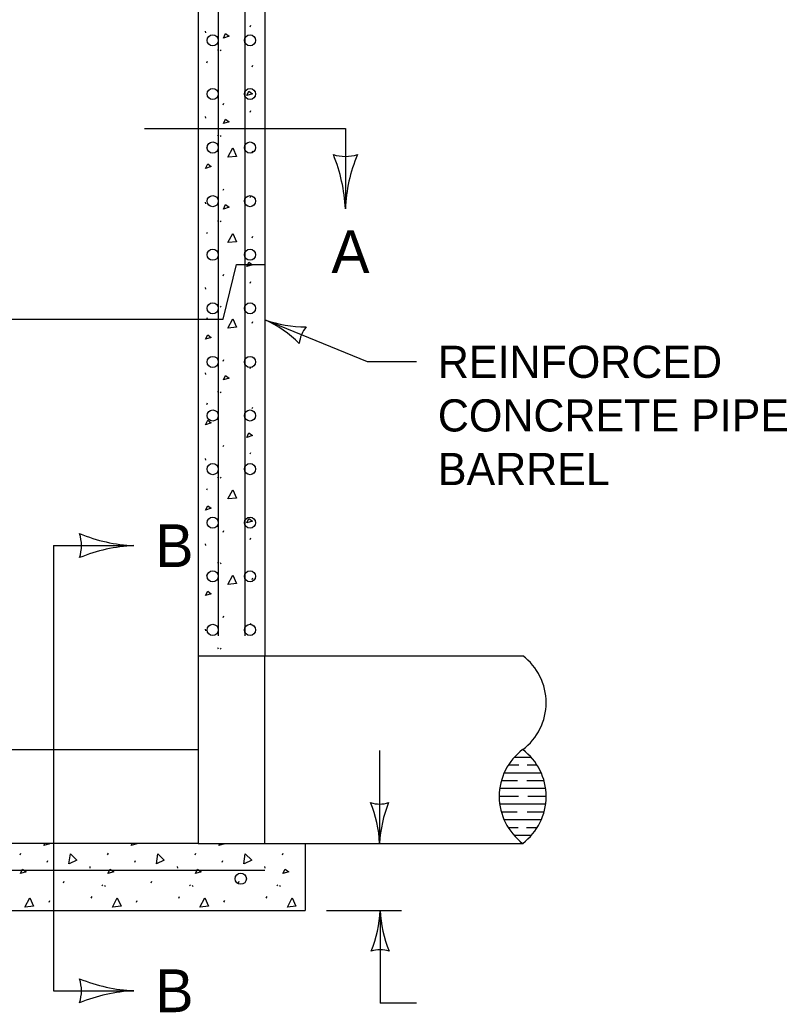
# Model space of a CAD drawing. Extents: x 49991.4 to 50028.3, y 49987.6 to 50011.4.
# Drawn here: x 50026.881 to 50028.313, y 49989.113 to 49990.964 of the extents above; entities that cross this region are included whole.
import ezdxf

# ---------------------------------------------------------------- set-up
doc = ezdxf.new("R2010")
doc.units = 0
for name, color, linetype in [('Level 1', 7, 'Continuous'), ('Level 2', 7, 'Continuous'), ('Level 3', 7, 'Continuous'), ('Level 4', 7, 'Continuous'), ('Level 6', 7, 'Continuous')]:
    doc.layers.add(name, color=color, linetype=linetype)

msp = doc.modelspace()

# ---------------------------------------------------------------- linework, layer by layer
at = {"layer": 'Level 1'}
for p, q in [((50027.3384, 49991.4777), (50027.3384, 49989.7777)), ((50027.2509, 49991.4401), (50027.2509, 49989.8151)), ((50027.3009, 49991.4401), (50027.3009, 49989.8151)), ((50027.2268, 49990.9433), (50027.2271, 49990.9403)), ((50027.3109, 49990.9516), (50027.3122, 49990.9546)), ((50027.2495, 49990.9091), (50027.2509, 49990.9071)), ((50027.2546, 49990.9083), (50027.2559, 49990.9063)), ((50027.2299, 49990.8844), (50027.2312, 49990.8874)), ((50027.3142, 49990.8767), (50027.3156, 49990.8797)), ((50027.2603, 49990.8058), (50027.2616, 49990.8088)), ((50027.3109, 49990.7922), (50027.3122, 49990.7952)), ((50027.2268, 49990.7838), (50027.2271, 49990.7808)), ((50027.2495, 49990.7497), (50027.2509, 49990.7477)), ((50027.2546, 49990.7489), (50027.2559, 49990.7469)), ((50027.2299, 49990.7249), (50027.2312, 49990.7279)), ((50027.3142, 49990.7173), (50027.3156, 49990.7203)), ((50027.2603, 49990.6464), (50027.2616, 49990.6494)), ((50027.2268, 49990.6243), (50027.2271, 49990.6213)), ((50027.3109, 49990.6327), (50027.3122, 49990.6357)), ((50027.2495, 49990.5902), (50027.2509, 49990.5882)), ((50027.2546, 49990.5894), (50027.2559, 49990.5874)), ((50027.2299, 49990.5655), (50027.2312, 49990.5685)), ((50027.3142, 49990.5579), (50027.3156, 49990.5609)), ((50027.2602, 49990.4059), (50027.2855, 49990.5077)), ((50027.2855, 49990.5077), (50027.3384, 49990.5077)), ((50027.2603, 49990.4869), (50027.2616, 49990.4899)), ((50027.3109, 49990.4733), (50027.3122, 49990.4763)), ((50027.2268, 49990.4649), (50027.2271, 49990.4619)), ((50027.2495, 49990.4307), (50027.2509, 49990.4287)), ((50027.2546, 49990.43), (50027.2559, 49990.428)), ((50025.9916, 49990.4059), (50027.2602, 49990.4059)), ((50027.2299, 49990.4061), (50027.2312, 49990.4091)), ((50027.3142, 49990.3984), (50027.3156, 49990.4014)), ((50027.2603, 49990.3275), (50027.2616, 49990.3305)), ((50027.3109, 49990.3138), (50027.3122, 49990.3168)), ((50027.2268, 49990.3055), (50027.2271, 49990.3025)), ((50027.2495, 49990.2713), (50027.2509, 49990.2693)), ((50027.2546, 49990.2705), (50027.2559, 49990.2685)), ((50027.2299, 49990.2466), (50027.2312, 49990.2496)), ((50027.3142, 49990.2389), (50027.3156, 49990.2419)), ((50027.2603, 49990.168), (50027.2616, 49990.171)), ((50027.2268, 49990.146), (50027.2271, 49990.143)), ((50027.3109, 49990.1543), (50027.3122, 49990.1573)), ((50027.2495, 49990.1118), (50027.2509, 49990.1098)), ((50027.2546, 49990.1111), (50027.2559, 49990.1091)), ((50027.2299, 49990.0871), (50027.2312, 49990.0901)), ((50027.2603, 49990.0085), (50027.2616, 49990.0115)), ((50027.3109, 49989.9949), (50027.3122, 49989.9979)), ((50027.2268, 49989.9865), (50027.2271, 49989.9835)), ((50027.2495, 49989.9524), (50027.2509, 49989.9504)), ((50027.2546, 49989.9516), (50027.2559, 49989.9496)), ((50027.2299, 49989.9277), (50027.2312, 49989.9307)), ((50027.3142, 49989.92), (50027.3156, 49989.923)), ((50027.2603, 49989.8491), (50027.2616, 49989.8521)), ((50027.2268, 49989.8271), (50027.2271, 49989.8241)), ((50027.3109, 49989.8355), (50027.3122, 49989.8385)), ((50027.2495, 49989.7929), (50027.2509, 49989.7909)), ((50027.2546, 49989.7921), (50027.2559, 49989.7901)), ((50027.2134, 49989.7777), (50027.8193, 49989.7777)), ((50026.0384, 49989.6027), (50027.2134, 49989.6027)), ((50027.8352, 49989.5882), (50027.8034, 49989.5882)), ((50027.8122, 49989.5736), (50027.7924, 49989.5736)), ((50027.8462, 49989.5736), (50027.8279, 49989.5736)), ((50027.8539, 49989.559), (50027.7846, 49989.559)), ((50027.8099, 49989.5444), (50027.7795, 49989.5444)), ((50027.8591, 49989.5444), (50027.8271, 49989.5444)), ((50027.8115, 49989.5152), (50027.7755, 49989.5152)), ((50027.8621, 49989.5298), (50027.7765, 49989.5298)), ((50027.863, 49989.5152), (50027.8287, 49989.5152)), ((50027.8621, 49989.5007), (50027.7765, 49989.5007)), ((50027.8092, 49989.4861), (50027.7795, 49989.4861)), ((50027.8591, 49989.4861), (50027.8279, 49989.4861)), ((50027.8539, 49989.4715), (50027.7846, 49989.4715)), ((50027.8108, 49989.4569), (50027.7924, 49989.4569)), ((50027.8462, 49989.4569), (50027.8264, 49989.4569)), ((50027.8352, 49989.4423), (50027.8034, 49989.4423)), ((50027.2134, 49989.4277), (50027.8193, 49989.4277)), ((50027.4134, 49989.4277), (50027.4134, 49989.3027)), ((50026.8815, 49989.4064), (50026.8828, 49989.4094)), ((50027.0447, 49989.4064), (50027.0461, 49989.4094)), ((50027.208, 49989.4064), (50027.2093, 49989.4094)), ((50027.3713, 49989.4064), (50027.3726, 49989.4094)), ((50026.9321, 49989.3928), (50026.9334, 49989.3958)), ((50027.0113, 49989.3844), (50027.0116, 49989.3814)), ((50027.0953, 49989.3928), (50027.0967, 49989.3958)), ((50027.1745, 49989.3844), (50027.1749, 49989.3814)), ((50027.2586, 49989.3928), (50027.2599, 49989.3958)), ((50027.3378, 49989.3844), (50027.3381, 49989.3814)), ((50025.9134, 49989.3777), (50027.3384, 49989.3777)), ((50026.9624, 49989.3541), (50026.9637, 49989.3571)), ((50027.034, 49989.3503), (50027.0353, 49989.3483)), ((50027.0391, 49989.3495), (50027.0404, 49989.3475)), ((50027.1257, 49989.3541), (50027.127, 49989.3571)), ((50027.1973, 49989.3503), (50027.1986, 49989.3483)), ((50027.2023, 49989.3495), (50027.2037, 49989.3475)), ((50027.2889, 49989.3541), (50027.2903, 49989.3571)), ((50027.3605, 49989.3503), (50027.3619, 49989.3483)), ((50027.3656, 49989.3495), (50027.3669, 49989.3475)), ((50027.0143, 49989.3256), (50027.0157, 49989.3285)), ((50027.1776, 49989.3256), (50027.1789, 49989.3285)), ((50027.3409, 49989.3256), (50027.3422, 49989.3285)), ((50026.9354, 49989.3179), (50026.9367, 49989.3209)), ((50027.0987, 49989.3179), (50027.1, 49989.3209)), ((50027.2619, 49989.3179), (50027.2633, 49989.3209)), ((50025.8384, 49989.3027), (50027.4134, 49989.3027))]:
    msp.add_line(p, q, dxfattribs=at)
msp.add_lwpolyline([(50026.0384, 49991.4777), (50027.2134, 49991.4777), (50027.2134, 49989.4277), (50026.0384, 49989.4277)], close=True, dxfattribs=at)
for points in [[(50027.2609, 49990.9303), (50027.2649, 49990.9387), (50027.2716, 49990.9337), (50027.2609, 49990.9303)], [(50027.3043, 49990.823), (50027.3083, 49990.8313), (50027.315, 49990.8263), (50027.3043, 49990.823)], [(50027.2609, 49990.7709), (50027.2649, 49990.7792), (50027.2716, 49990.7742), (50027.2609, 49990.7709)], [(50027.2693, 49990.7083), (50027.2783, 49990.7253), (50027.2853, 49990.7097), (50027.2696, 49990.7083)], [(50027.2275, 49990.6873), (50027.2315, 49990.6957), (50027.2382, 49990.6907), (50027.2275, 49990.6873)], [(50027.2609, 49990.6114), (50027.2649, 49990.6197), (50027.2716, 49990.6147), (50027.2609, 49990.6114)], [(50027.2693, 49990.5489), (50027.2783, 49990.5659), (50027.2853, 49990.5502), (50027.2696, 49990.5489)], [(50027.3043, 49990.5041), (50027.3083, 49990.5124), (50027.315, 49990.5074), (50027.3043, 49990.5041)], [(50027.2693, 49990.3894), (50027.2783, 49990.4064), (50027.2853, 49990.3907), (50027.2696, 49990.3894)], [(50027.2275, 49990.3684), (50027.2315, 49990.3767), (50027.2382, 49990.3717), (50027.2275, 49990.3684)], [(50027.2609, 49990.2925), (50027.2649, 49990.3008), (50027.2716, 49990.2958), (50027.2609, 49990.2925)], [(50027.2275, 49990.209), (50027.2315, 49990.2173), (50027.2382, 49990.2123), (50027.2275, 49990.209)], [(50027.3043, 49990.1851), (50027.3083, 49990.1935), (50027.315, 49990.1885), (50027.3043, 49990.1851)], [(50027.2693, 49990.0705), (50027.2783, 49990.0875), (50027.2853, 49990.0718), (50027.2696, 49990.0705)], [(50027.2275, 49990.0495), (50027.2315, 49990.0578), (50027.2382, 49990.0529), (50027.2275, 49990.0495)], [(50027.3043, 49990.0257), (50027.3083, 49990.034), (50027.315, 49990.029), (50027.3043, 49990.0257)], [(50027.2693, 49989.911), (50027.2783, 49989.928), (50027.2853, 49989.9124), (50027.2696, 49989.911)], [(50027.2275, 49989.8901), (50027.2315, 49989.8984), (50027.2382, 49989.8934), (50027.2275, 49989.8901)], [(50026.9255, 49989.4236), (50026.9274, 49989.4277)], [(50026.9351, 49989.4277), (50026.9361, 49989.4269), (50026.9255, 49989.4236)], [(50027.0887, 49989.4236), (50027.0907, 49989.4277)], [(50027.0984, 49989.4277), (50027.0994, 49989.4269), (50027.0887, 49989.4236)], [(50027.252, 49989.4236), (50027.2539, 49989.4277)], [(50027.2617, 49989.4277), (50027.2627, 49989.4269), (50027.252, 49989.4236)], [(50026.9726, 49989.3893), (50026.9752, 49989.4084), (50026.9871, 49989.3961), (50026.9729, 49989.3895)], [(50027.1359, 49989.3893), (50027.1385, 49989.4084), (50027.1504, 49989.3961), (50027.1362, 49989.3895)], [(50027.2991, 49989.3893), (50027.3017, 49989.4084), (50027.3137, 49989.3961), (50027.2994, 49989.3895)], [(50026.8821, 49989.3715), (50026.8861, 49989.3798), (50026.8928, 49989.3748), (50026.8821, 49989.3715)], [(50027.0454, 49989.3715), (50027.0494, 49989.3798), (50027.0561, 49989.3748), (50027.0454, 49989.3715)], [(50027.2087, 49989.3715), (50027.2127, 49989.3798), (50027.2193, 49989.3748), (50027.2087, 49989.3715)], [(50027.3719, 49989.3715), (50027.3759, 49989.3798), (50027.3826, 49989.3748), (50027.3719, 49989.3715)], [(50026.8905, 49989.3089), (50026.8995, 49989.3259), (50026.9064, 49989.3103), (50026.8908, 49989.3089)], [(50027.0537, 49989.3089), (50027.0627, 49989.3259), (50027.0697, 49989.3103), (50027.0541, 49989.3089)], [(50027.217, 49989.3089), (50027.226, 49989.3259), (50027.233, 49989.3103), (50027.2173, 49989.3089)], [(50027.3803, 49989.3089), (50027.3892, 49989.3259), (50027.3962, 49989.3103), (50027.3806, 49989.3089)]]:
    msp.add_lwpolyline(points, dxfattribs=at)
for centre in [(50027.2409, 49990.9261), (50027.3105, 49990.9261), (50027.2409, 49990.8261), (50027.3105, 49990.8261), (50027.2409, 49990.7261), (50027.3105, 49990.7261), (50027.2409, 49990.6261), (50027.3105, 49990.6261), (50027.2409, 49990.5261), (50027.3105, 49990.5261), (50027.2409, 49990.4261), (50027.3105, 49990.4261), (50027.2409, 49990.3261), (50027.3105, 49990.3261), (50027.2409, 49990.2261), (50027.3105, 49990.2261), (50027.2409, 49990.1261), (50027.3105, 49990.1261), (50027.2409, 49990.0261), (50027.3105, 49990.0261), (50027.2409, 49989.9261), (50027.3105, 49989.9261), (50027.2409, 49989.8261), (50027.3105, 49989.8261), (50027.2932, 49989.3617)]:
    msp.add_circle(centre, 0.0104, dxfattribs=at)
for centre, start, end in [((50027.7537, 49989.6902), 306.8699, 53.1301), ((50027.8849, 49989.5152), 126.8699, 233.1301), ((50027.7537, 49989.5152), 306.8699, 53.1301)]:
    msp.add_arc(centre, 0.1094, start, end, dxfattribs=at)
at = {"layer": 'Level 3'}
for p, q in [((50027.5298, 49990.3263), (50027.3384, 49990.4046)), ((50027.621, 49990.3263), (50027.5298, 49990.3263)), ((50027.5524, 49989.6011), (50027.5524, 49989.4277)), ((50027.4534, 49989.3027), (50027.5934, 49989.3027)), ((50027.5534, 49989.3027), (50027.5534, 49989.1293)), ((50027.621, 49989.1293), (50027.5534, 49989.1293))]:
    msp.add_line(p, q, dxfattribs=at)
for centre, radius, start, end in [((50027.4884, 49990.7826), 0.073, 252.1388, 287.8612), ((50027.1781, 49990.5963), 0.3107, 2.8273, 22.0772), ((50027.4884, 49990.7826), 0.073, 252.1388, 287.8612), ((50027.1781, 49990.5963), 0.3107, 2.8273, 22.0772), ((50027.7846, 49990.5994), 0.2964, 157.456, 177.6395), ((50027.7846, 49990.5994), 0.2964, 157.456, 177.6395), ((50027.2458, 49990.2025), 0.2223, 45.207, 65.3905), ((50027.4159, 49990.6244), 0.233, 250.5783, 269.8281), ((50027.4571, 49990.3561), 0.0548, 139.8898, 175.6122), ((50027.106, 49990.2795), 0.2964, 247.456, 267.6395), ((50026.9229, 49989.9833), 0.073, 342.1388, 17.8612), ((50027.1091, 49989.673), 0.3107, 92.8273, 112.0772), ((50027.5524, 49989.5559), 0.0548, 252.1388, 287.8612), ((50027.3197, 49989.4162), 0.233, 2.8273, 22.0772), ((50027.7745, 49989.4186), 0.2223, 157.456, 177.6395), ((50027.3313, 49989.3119), 0.2223, 337.456, 357.6395), ((50027.7861, 49989.3142), 0.233, 182.8273, 202.0772), ((50027.5534, 49989.1745), 0.0548, 72.1388, 107.8612), ((50027.106, 49989.4489), 0.2964, 247.456, 267.6395), ((50026.9229, 49989.1527), 0.073, 342.1388, 17.8612), ((50027.1091, 49988.8424), 0.3107, 92.8273, 112.0772)]:
    msp.add_arc(centre, radius, start, end, dxfattribs=at)
at = {"layer": 'Level 4'}
msp.add_line((50027.3384, 49989.4277), (50027.3384, 49989.7777), dxfattribs=at)
at = {"layer": 'Level 6'}
for p, q in [((50027.1134, 49990.7617), (50027.4884, 49990.7617)), ((50027.4884, 49990.7617), (50027.4884, 49990.6117)), ((50026.9438, 49989.9833), (50026.9438, 49989.1527)), ((50026.9438, 49989.9833), (50027.0938, 49989.9833)), ((50026.9438, 49989.1527), (50027.0938, 49989.1527))]:
    msp.add_line(p, q, dxfattribs=at)

# ---------------------------------------------------------------- texts
at = {"layer": 'Level 2'}
for s, height, p in [('A', 0.0799, (50027.4623, 49990.4918)), ('REINFORCED', 0.06, (50027.661, 49990.2963)), ('CONCRETE PIPE', 0.06, (50027.661, 49990.1963)), ('BARREL', 0.06, (50027.661, 49990.0963)), ('B', 0.0799, (50027.1338, 49989.9433)), ('B', 0.0799, (50027.1338, 49989.1127))]:
    msp.add_text(s, height=height, dxfattribs=at).set_placement(p)

doc.saveas('drawing.dxf')
